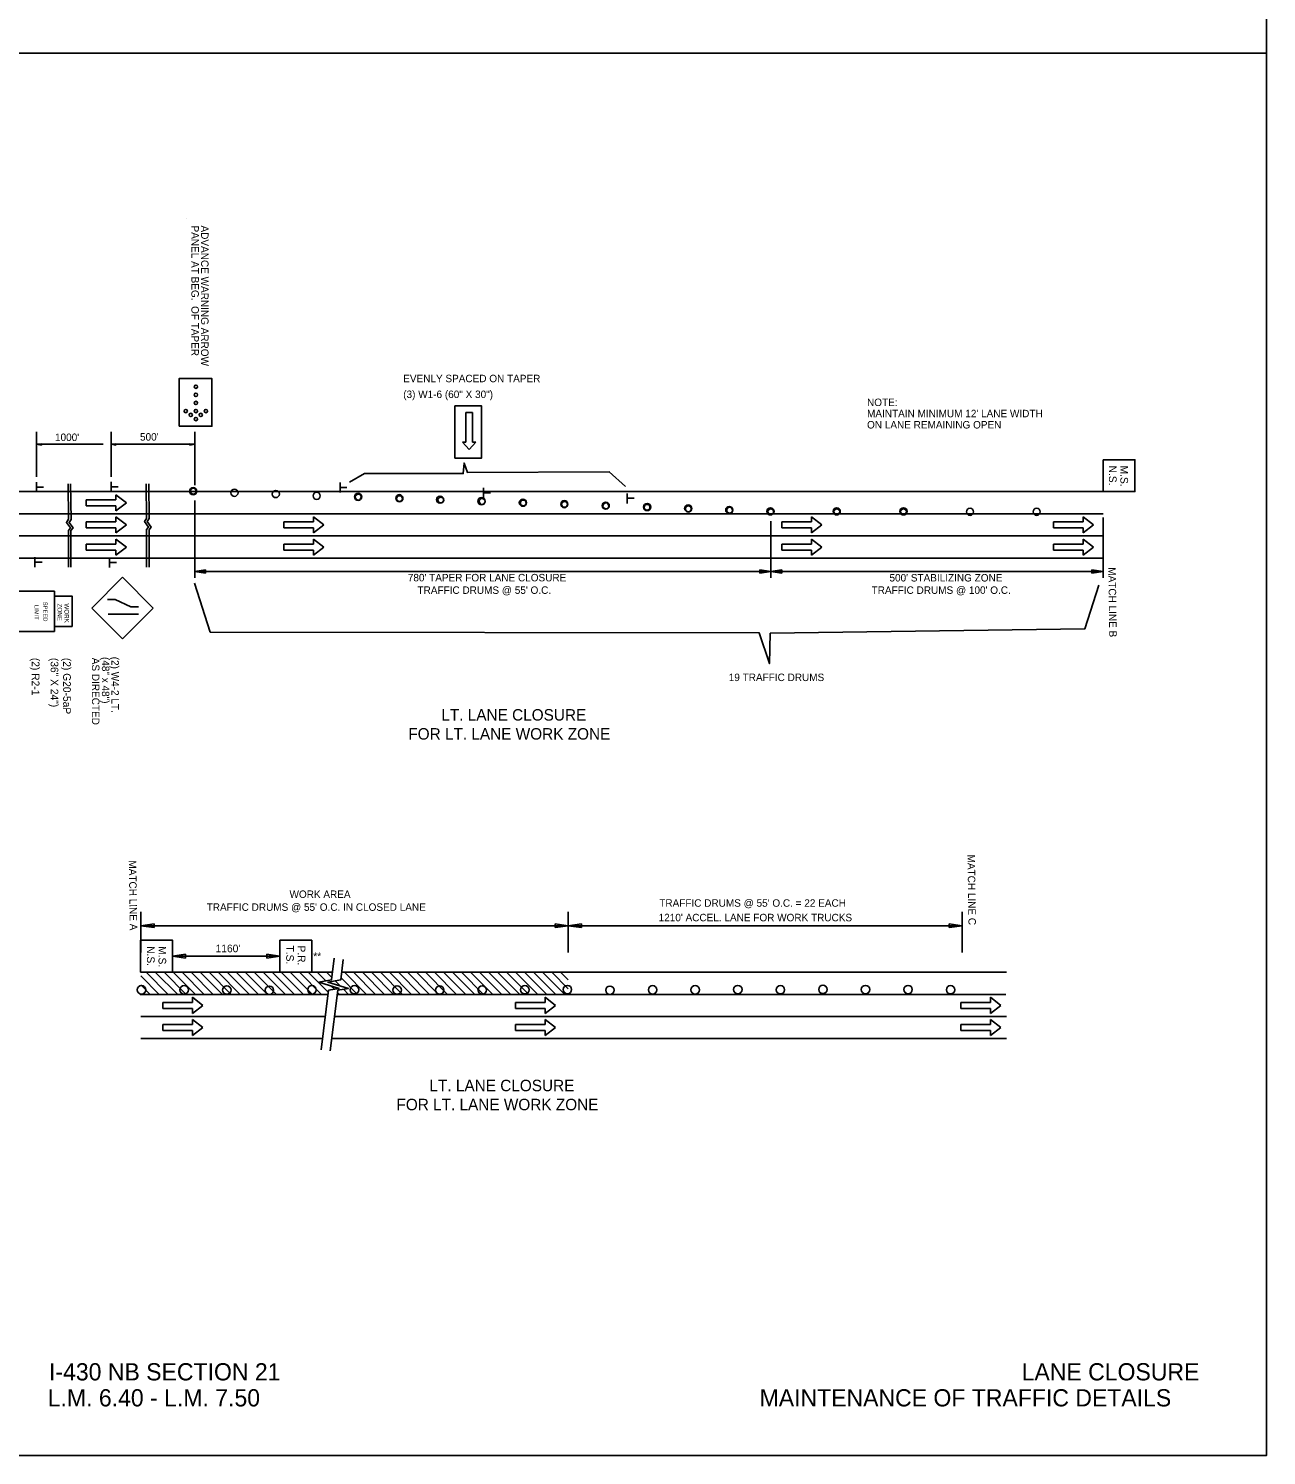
# Model space of a CAD drawing. Extents: x -100 to 745, y -1581 to -107.
# Drawn here: x 647.6 to 744.8, y -486.8 to -374.9 of the extents above; entities that cross this region are included whole.
import ezdxf

# ---------------------------------------------------------------- set-up
doc = ezdxf.new("R2010")
doc.units = 0
for name, color, linetype in [('Default', 7, 'Continuous'), ('R_Border', 7, 'Continuous'), ('R_Proposed Road', 7, 'Continuous'), ('R_ROW', 7, 'Continuous'), ('R_ROW Annot', 7, 'Continuous')]:
    doc.layers.add(name, color=color, linetype=linetype)

msp = doc.modelspace()

# ---------------------------------------------------------------- linework, layer by layer
at = {"layer": 'Default'}
for p, q in [((681.95, -404.99), (681.95, -407.32)), ((681.95, -404.99), (682.47, -404.99)), ((682.47, -404.99), (682.47, -407.32)), ((648.28, -406.5), (648.28, -410.02)), ((654.13, -406.5), (654.13, -410.02)), ((660.68, -406.5), (660.68, -410.69)), ((681.95, -407.32), (681.7, -407.32)), ((681.7, -407.32), (682.21, -407.89)), ((682.21, -407.89), (682.73, -407.32)), ((682.47, -407.32), (682.73, -407.32)), ((648.65, -407.43), (648.28, -407.48)), ((648.28, -407.48), (653.5, -407.48)), ((648.65, -407.54), (648.28, -407.48)), ((648.65, -407.44), (648.34, -407.48)), ((648.65, -407.53), (648.34, -407.48)), ((648.65, -407.45), (648.4, -407.48)), ((648.65, -407.52), (648.4, -407.48)), ((648.65, -407.45), (648.47, -407.48)), ((648.65, -407.51), (648.47, -407.48)), ((648.65, -407.46), (648.53, -407.48)), ((648.65, -407.5), (648.53, -407.48)), ((648.65, -407.47), (648.59, -407.48)), ((648.65, -407.49), (648.59, -407.48)), ((648.65, -407.54), (648.65, -407.43)), ((654.5, -407.43), (654.13, -407.48)), ((654.13, -407.48), (660.68, -407.48)), ((654.5, -407.54), (654.13, -407.48)), ((654.5, -407.44), (654.19, -407.48)), ((654.5, -407.53), (654.19, -407.48)), ((654.5, -407.45), (654.25, -407.48)), ((654.5, -407.52), (654.25, -407.48)), ((654.5, -407.45), (654.32, -407.48)), ((654.5, -407.51), (654.32, -407.48)), ((654.5, -407.46), (654.38, -407.48)), ((654.5, -407.5), (654.38, -407.48)), ((654.5, -407.47), (654.44, -407.48)), ((654.5, -407.49), (654.44, -407.48)), ((654.5, -407.54), (654.5, -407.43)), ((660.3, -407.43), (660.68, -407.48)), ((660.3, -407.43), (660.3, -407.54)), ((660.3, -407.44), (660.61, -407.48)), ((660.3, -407.45), (660.55, -407.48)), ((660.3, -407.45), (660.49, -407.48)), ((660.3, -407.46), (660.42, -407.48)), ((660.3, -407.47), (660.36, -407.48)), ((660.3, -407.54), (660.68, -407.48)), ((660.3, -407.5), (660.42, -407.48)), ((660.3, -407.52), (660.55, -407.48)), ((660.3, -407.53), (660.61, -407.48)), ((660.3, -407.51), (660.49, -407.48)), ((660.3, -407.49), (660.36, -407.48)), ((648.28, -411.22), (648.28, -410.44)), ((654.13, -411.2), (654.13, -410.42)), ((672.08, -410.47), (672.08, -411.25)), ((644.68, -411.19), (660.68, -411.19)), ((648.29, -410.83), (648.82, -410.83)), ((654.5, -411.83), (652.17, -411.83)), ((652.17, -411.83), (652.17, -412.3)), ((654.14, -410.81), (654.67, -410.81)), ((654.5, -411.43), (654.5, -411.83)), ((654.5, -411.43), (655.32, -412.06)), ((660.68, -411.19), (731.95, -411.19)), ((672.09, -410.86), (672.62, -410.86)), ((683.35, -410.9), (683.35, -411.68)), ((683.36, -411.29), (683.89, -411.29)), ((694.62, -411.33), (694.62, -412.11)), ((694.63, -411.71), (695.16, -411.71)), ((644.68, -412.93), (660.68, -412.93)), ((654.5, -412.3), (652.17, -412.3)), ((655.32, -412.06), (654.5, -412.7)), ((654.5, -412.3), (654.5, -412.7)), ((660.68, -417.94), (660.68, -411.9)), ((660.68, -412.93), (731.95, -412.93)), ((654.5, -413.57), (652.17, -413.57)), ((652.17, -413.57), (652.17, -414.04)), ((654.5, -414.04), (652.17, -414.04)), ((654.5, -413.17), (654.5, -413.57)), ((654.5, -413.17), (655.32, -413.8)), ((655.32, -413.8), (654.5, -414.43)), ((654.5, -414.04), (654.5, -414.43)), ((669.99, -413.57), (667.67, -413.57)), ((667.67, -413.57), (667.67, -414.04)), ((669.99, -414.04), (667.67, -414.04)), ((669.99, -413.17), (669.99, -413.57)), ((669.99, -413.17), (670.81, -413.8)), ((670.81, -413.8), (669.99, -414.43)), ((669.99, -414.04), (669.99, -414.43)), ((705.88, -417.94), (705.88, -413.51)), ((709.07, -413.57), (706.75, -413.57)), ((706.75, -413.57), (706.75, -414.04)), ((709.07, -414.04), (706.75, -414.04)), ((709.07, -413.17), (709.07, -413.57)), ((709.07, -413.17), (709.89, -413.8)), ((709.89, -413.8), (709.07, -414.43)), ((709.07, -414.04), (709.07, -414.43)), ((730.39, -413.57), (728.07, -413.57)), ((728.07, -413.57), (728.07, -414.04)), ((730.39, -414.04), (728.07, -414.04)), ((730.39, -413.17), (730.39, -413.57)), ((730.39, -413.17), (731.21, -413.8)), ((731.21, -413.8), (730.39, -414.43)), ((730.39, -414.04), (730.39, -414.43)), ((731.95, -413.23), (731.95, -417.95)), ((644.68, -414.67), (660.68, -414.67)), ((654.5, -414.91), (654.5, -415.3)), ((654.5, -414.91), (655.32, -415.54)), ((660.68, -414.67), (731.95, -414.67)), ((669.99, -414.91), (669.99, -415.3)), ((669.99, -414.91), (670.81, -415.54)), ((709.07, -414.91), (709.07, -415.3)), ((709.07, -414.91), (709.89, -415.54)), ((730.39, -414.91), (730.39, -415.3)), ((730.39, -414.91), (731.21, -415.54)), ((648.15, -417.11), (648.15, -416.32)), ((654.5, -415.3), (652.17, -415.3)), ((652.17, -415.3), (652.17, -415.78)), ((654.5, -415.78), (652.17, -415.78)), ((655.32, -415.54), (654.5, -416.17)), ((654.5, -415.78), (654.5, -416.17)), ((669.99, -415.3), (667.67, -415.3)), ((667.67, -415.3), (667.67, -415.78)), ((669.99, -415.78), (667.67, -415.78)), ((670.81, -415.54), (669.99, -416.17)), ((669.99, -415.78), (669.99, -416.17)), ((709.07, -415.3), (706.75, -415.3)), ((706.75, -415.3), (706.75, -415.78)), ((709.07, -415.78), (706.75, -415.78)), ((709.89, -415.54), (709.07, -416.17)), ((709.07, -415.78), (709.07, -416.17)), ((730.39, -415.3), (728.07, -415.3)), ((728.07, -415.3), (728.07, -415.78)), ((730.39, -415.78), (728.07, -415.78)), ((731.21, -415.54), (730.39, -416.17)), ((730.39, -415.78), (730.39, -416.17)), ((644.68, -416.41), (660.68, -416.41)), ((648.16, -416.72), (648.7, -416.72)), ((654, -417.13), (654, -416.35)), ((654.01, -416.74), (654.55, -416.74)), ((660.68, -416.41), (731.95, -416.41)), ((661.54, -417.32), (660.68, -417.45)), ((661.54, -417.58), (661.54, -417.32)), ((705.88, -417.45), (705.01, -417.32)), ((705.01, -417.32), (705.01, -417.58)), ((706.75, -417.32), (705.88, -417.45)), ((706.75, -417.58), (706.75, -417.32)), ((731.95, -417.45), (731.08, -417.32)), ((731.08, -417.32), (731.08, -417.58)), ((655.01, -417.91), (652.6, -420.32)), ((655.01, -417.91), (657.42, -420.32)), ((705.88, -417.45), (660.68, -417.45)), ((660.68, -417.45), (661.54, -417.58)), ((705.01, -417.58), (705.88, -417.45)), ((731.95, -417.45), (705.88, -417.45)), ((705.88, -417.45), (706.75, -417.58)), ((731.08, -417.58), (731.95, -417.45)), ((653.84, -419.66), (654.45, -419.66)), ((654.45, -419.66), (655.68, -420.22)), ((652.6, -420.32), (655.01, -422.73)), ((653.89, -420.79), (656.26, -420.79)), ((657.42, -420.32), (655.01, -422.73)), ((655.68, -420.22), (656.26, -420.22)), ((656.46, -444.16), (656.46, -447.35)), ((689.99, -444.16), (689.99, -447.35)), ((720.9, -444.16), (720.9, -447.35)), ((656.46, -445.24), (657.49, -445.09)), ((689.99, -445.24), (656.46, -445.24)), ((657.49, -445.39), (656.46, -445.24)), ((657.49, -445.09), (657.49, -445.39)), ((688.96, -445.39), (688.96, -445.09)), ((688.96, -445.09), (689.99, -445.24)), ((689.99, -445.24), (688.96, -445.39)), ((689.99, -445.24), (691.02, -445.09)), ((720.9, -445.24), (689.99, -445.24)), ((691.02, -445.39), (689.99, -445.24)), ((691.02, -445.09), (691.02, -445.39)), ((719.87, -445.39), (719.87, -445.09)), ((719.87, -445.09), (720.9, -445.24)), ((720.9, -445.24), (719.87, -445.39)), ((656.46, -445.9), (656.46, -447.35)), ((656.46, -446.83), (656.46, -447.35)), ((658.94, -447.63), (659.97, -447.47)), ((667.36, -447.63), (658.94, -447.63)), ((659.97, -447.78), (658.94, -447.63)), ((659.97, -447.47), (659.97, -447.78)), ((666.33, -447.78), (666.33, -447.47)), ((666.33, -447.47), (667.36, -447.63)), ((667.36, -447.63), (666.33, -447.78)), ((656.44, -448.88), (671.5, -448.88)), ((656.46, -449.18), (657.9, -450.62)), ((656.46, -449.88), (657.19, -450.62)), ((656.87, -448.88), (658.6, -450.62)), ((657.57, -448.88), (659.37, -450.67)), ((658.28, -448.88), (660.02, -450.62)), ((658.99, -448.88), (660.73, -450.62)), ((659.69, -448.88), (661.43, -450.62)), ((660.4, -448.88), (662.14, -450.62)), ((661.11, -448.88), (662.85, -450.62)), ((661.82, -448.88), (663.55, -450.62)), ((662.52, -448.88), (664.26, -450.62)), ((663.23, -448.88), (664.97, -450.62)), ((663.94, -448.88), (665.68, -450.62)), ((664.64, -448.88), (666.38, -450.62)), ((665.35, -448.88), (667.09, -450.62)), ((666.06, -448.88), (667.8, -450.62)), ((666.77, -448.88), (668.5, -450.62)), ((667.47, -448.88), (669.21, -450.62)), ((668.18, -448.88), (669.92, -450.62)), ((668.89, -448.88), (670.63, -450.62)), ((669.59, -448.88), (671.16, -450.45)), ((670.3, -448.88), (670.98, -449.56)), ((671.01, -448.88), (671.44, -449.31)), ((671.69, -449.56), (672.09, -449.96)), ((672.17, -449.33), (673.45, -450.62)), ((672.23, -448.88), (689.99, -448.88)), ((672.42, -448.88), (674.16, -450.62)), ((673.13, -448.88), (674.87, -450.62)), ((673.84, -448.88), (675.58, -450.62)), ((674.54, -448.88), (676.28, -450.62)), ((675.25, -448.88), (676.99, -450.62)), ((675.96, -448.88), (677.7, -450.62)), ((676.67, -448.88), (678.4, -450.62)), ((677.37, -448.88), (679.11, -450.62)), ((678.08, -448.88), (679.82, -450.62)), ((678.79, -448.88), (680.52, -450.62)), ((679.49, -448.88), (681.23, -450.62)), ((680.2, -448.88), (681.94, -450.62)), ((680.91, -448.88), (682.65, -450.62)), ((681.61, -448.88), (683.35, -450.62)), ((682.32, -448.88), (684.06, -450.62)), ((683.03, -448.88), (684.77, -450.62)), ((683.74, -448.88), (685.47, -450.62)), ((684.44, -448.88), (686.18, -450.62)), ((685.15, -448.88), (686.89, -450.62)), ((685.86, -448.88), (687.6, -450.62)), ((686.56, -448.88), (688.3, -450.62)), ((687.27, -448.88), (689.01, -450.62)), ((687.98, -448.88), (689.72, -450.62)), ((688.69, -448.88), (689.99, -450.19)), ((689.39, -448.88), (689.99, -449.48)), ((689.99, -448.88), (724.38, -448.88)), ((656.39, -450.62), (671.14, -450.62)), ((660.5, -451.25), (660.5, -450.85)), ((661.32, -451.49), (660.5, -450.85)), ((671.39, -449.97), (671.64, -450.22)), ((671.87, -450.62), (689.99, -450.62)), ((671.89, -450.47), (672.04, -450.62)), ((672.35, -450.22), (672.75, -450.62)), ((688.17, -451.25), (688.17, -450.85)), ((688.99, -451.49), (688.17, -450.85)), ((689.94, -450.62), (724.33, -450.62)), ((723.12, -451.25), (723.12, -450.85)), ((723.94, -451.49), (723.12, -450.85)), ((660.5, -451.25), (658.17, -451.25)), ((658.17, -451.72), (658.17, -451.25)), ((660.5, -451.72), (658.17, -451.72)), ((660.5, -452.12), (661.32, -451.49)), ((660.5, -452.12), (660.5, -451.72)), ((688.17, -451.25), (685.85, -451.25)), ((685.85, -451.72), (685.85, -451.25)), ((688.17, -451.72), (685.85, -451.72)), ((688.17, -452.12), (688.99, -451.49)), ((688.17, -452.12), (688.17, -451.72)), ((723.12, -451.25), (720.79, -451.25)), ((720.79, -451.72), (720.79, -451.25)), ((723.12, -451.72), (720.79, -451.72)), ((723.12, -452.12), (723.94, -451.49)), ((723.12, -452.12), (723.12, -451.72)), ((656.46, -452.35), (670.93, -452.35)), ((660.5, -452.99), (658.17, -452.99)), ((658.17, -453.46), (658.17, -452.99)), ((660.5, -452.99), (660.5, -452.59)), ((661.32, -453.22), (660.5, -452.59)), ((660.5, -453.86), (661.32, -453.22)), ((671.7, -452.35), (689.99, -452.35)), ((688.17, -452.99), (685.85, -452.99)), ((685.85, -453.46), (685.85, -452.99)), ((688.17, -452.99), (688.17, -452.59)), ((688.99, -453.22), (688.17, -452.59)), ((688.17, -453.86), (688.99, -453.22)), ((689.99, -452.35), (724.38, -452.35)), ((723.12, -452.99), (720.79, -452.99)), ((720.79, -453.46), (720.79, -452.99)), ((723.12, -452.99), (723.12, -452.59)), ((723.94, -453.22), (723.12, -452.59)), ((723.12, -453.86), (723.94, -453.22)), ((656.46, -454.09), (670.71, -454.09)), ((660.5, -453.46), (658.17, -453.46)), ((660.5, -453.86), (660.5, -453.46)), ((671.44, -454.09), (689.99, -454.09)), ((688.17, -453.46), (685.85, -453.46)), ((688.17, -453.86), (688.17, -453.46)), ((689.99, -454.09), (724.38, -454.09)), ((723.12, -453.46), (720.79, -453.46)), ((723.12, -453.86), (723.12, -453.46))]:
    msp.add_line(p, q, dxfattribs=at)
for points in [[(659.45, -406.06), (659.45, -402.33), (662.03, -402.33), (662.03, -406.06)], [(681.1, -408.56), (681.1, -404.47), (683.19, -404.47), (683.19, -408.56)], [(731.95, -408.69), (734.45, -408.69), (734.45, -411.19), (731.95, -411.19)], [(649.68, -422.17), (646.27, -422.17), (646.27, -419), (649.68, -419)], [(651.07, -421.78), (649.68, -421.78), (649.68, -419.4), (651.07, -419.4)], [(656.44, -446.38), (658.94, -446.38), (658.94, -448.88), (656.44, -448.88)], [(667.36, -446.38), (669.86, -446.38), (669.86, -448.88), (667.36, -448.88)]]:
    msp.add_lwpolyline(points, close=True, dxfattribs=at)
for points in [[(672.83, -410.45), (673.99, -409.77), (681.75, -409.77), (681.82, -408.95), (682.09, -409.7), (693.2, -409.63), (694.49, -410.79)], [(650.74, -410.58), (650.79, -413.36), (650.62, -413.6), (650.94, -414.03), (650.77, -414.23), (650.77, -417.12)], [(650.94, -410.58), (650.99, -413.37), (650.82, -413.61), (651.14, -414.04), (650.97, -414.24), (650.97, -417.12)], [(656.87, -410.58), (656.91, -413.29), (656.75, -413.54), (657.06, -413.97), (656.9, -414.17), (656.9, -417.12)], [(657.07, -410.58), (657.11, -413.3), (656.95, -413.54), (657.26, -413.98), (657.1, -414.18), (657.1, -417.12)], [(660.66, -418.38), (661.9, -422.21), (704.96, -422.26), (705.77, -424.68), (705.84, -422.3), (730.51, -421.96), (731.62, -418.53)], [(670.6, -454.96), (671.18, -450.3), (672.01, -450.16), (670.41, -449.67), (671.42, -449.48), (671.63, -447.79)], [(671.32, -455.05), (671.91, -450.3), (672.74, -450.16), (671.13, -449.67), (672.15, -449.48), (672.34, -447.89)]]:
    msp.add_lwpolyline(points, dxfattribs=at)
for centre, radius in [((660.77, -402.97), 0.131), ((660.77, -403.6), 0.131), ((659.98, -404.87), 0.131), ((660.37, -405.18), 0.131), ((660.77, -404.23), 0.131), ((660.77, -404.87), 0.131), ((661.16, -405.18), 0.131), ((661.56, -404.87), 0.131), ((660.77, -405.5), 0.131), ((660.56, -411.16), 0.281), ((660.57, -411.16), 0.229), ((663.8, -411.28), 0.281), ((667.04, -411.38), 0.281), ((670.25, -411.52), 0.281), ((673.5, -411.6), 0.281), ((673.51, -411.62), 0.229), ((676.74, -411.71), 0.281), ((676.75, -411.74), 0.229), ((679.93, -411.82), 0.281), ((679.99, -411.85), 0.229), ((683.18, -411.94), 0.281), ((683.23, -411.96), 0.229), ((686.43, -412.06), 0.281), ((686.46, -412.08), 0.229), ((689.68, -412.17), 0.281), ((689.7, -412.19), 0.229), ((692.93, -412.29), 0.281), ((692.94, -412.31), 0.229), ((696.18, -412.4), 0.281), ((696.17, -412.42), 0.229), ((699.4, -412.51), 0.281), ((699.41, -412.54), 0.229), ((702.62, -412.63), 0.281), ((702.65, -412.65), 0.229), ((705.85, -412.74), 0.281), ((705.87, -412.77), 0.229), ((705.88, -412.77), 0.229), ((711.05, -412.74), 0.281), ((711.06, -412.77), 0.229), ((716.29, -412.74), 0.281), ((716.29, -412.77), 0.229), ((721.51, -412.77), 0.281), ((726.74, -412.77), 0.281), ((709.97, -450.23), 0.333), ((656.51, -450.27), 0.333), ((659.85, -450.27), 0.333), ((663.2, -450.28), 0.333), ((666.54, -450.3), 0.333), ((669.88, -450.27), 0.333), ((673.22, -450.26), 0.333), ((676.56, -450.28), 0.333), ((679.9, -450.28), 0.333), ((683.24, -450.28), 0.333), ((686.58, -450.26), 0.333), ((689.92, -450.25), 0.333), ((693.26, -450.3), 0.333), ((696.61, -450.27), 0.333), ((699.95, -450.27), 0.333), ((703.29, -450.25), 0.333), ((706.63, -450.26), 0.333), ((713.31, -450.25), 0.333), ((716.65, -450.25), 0.333), ((719.99, -450.26), 0.333)]:
    msp.add_circle(centre, radius, dxfattribs=at)
at = {"layer": 'R_Proposed Road'}
for points in [[(574.77, -266.79), (574.77, -376.79), (744.77, -376.79), (744.77, -266.79)], [(574.77, -376.79), (574.77, -486.79), (744.77, -486.79), (744.77, -376.79)]]:
    msp.add_lwpolyline(points, close=True, dxfattribs=at)
at = {"layer": 'R_ROW Annot'}
msp.add_line((660.05, -389.8), (660.05, -389.8), dxfattribs=at)
msp.add_line((660.05, -389.8), (660.05, -389.8), dxfattribs=at)

# ---------------------------------------------------------------- texts
at = {"layer": 'Default'}
for s, height, rotation, p in [('PANEL AT BEG.  OF TAPER', 0.5862, 270, (660.42, -390.32)), ('ADVANCE WARNING ARROW', 0.5862, 270, (661.18, -390.32)), ('EVENLY SPACED ON TAPER', 0.5862, 359.9925, (677.04, -402.61)), ('(3) W1-6 (60" X 30")', 0.5862, 359.9925, (677.04, -403.85)), ('N.S.', 0.6, 270, (732.41, -409.15)), ('M.S.', 0.6, 270, (733.31, -409.15)), ('MATCH LINE B', 0.5862, 270.8059, (732.36, -417.13)), ('LIMIT', 0.33, 270, (648.12, -420.08)), ('SPEED', 0.33, 270, (648.8, -419.83)), ('ZONE', 0.354, 270.1004, (649.92, -419.97)), ('WORK', 0.354, 270.1004, (650.46, -419.96)), ('(2) R2-1', 0.6, 270, (647.9, -424.23)), ('(36" X 24")', 0.6, 270, (649.38, -424.23)), ('(2) G20-5aP', 0.6, 270, (650.36, -424.23)), ('AS DIRECTED ', 0.5862, 270, (652.62, -424.22)), ('(48" x 48")', 0.5862, 270, (653.4, -424.16)), ('(2) W4-2 LT.', 0.5862, 270, (654.15, -424.14)), ('MATCH LINE C', 0.5862, 270.8059, (721.31, -439.66)), ('MATCH LINE A', 0.5862, 270.8059, (655.51, -440.12)), ('N.S.', 0.6, 270, (656.94, -446.84)), ('M.S.', 0.6, 270, (657.84, -446.84)), ('T.S.', 0.6, 270, (667.86, -446.79)), ('P.R.', 0.6, 270, (668.76, -446.79))]:
    msp.add_text(s, height=height, rotation=rotation, dxfattribs=at).set_placement(p)
for s, height, p in [('NOTE:', 0.586, (713.43, -404.48)), ("MAINTAIN MINIMUM 12' LANE WIDTH", 0.5862, (713.43, -405.36)), ('ON LANE REMAINING OPEN', 0.5862, (713.43, -406.24)), ("1000'", 0.586, (649.72, -407.22)), ("500'", 0.586, (656.39, -407.19)), ("780' TAPER FOR LANE CLOSURE", 0.5862, (677.4, -418.23)), ("500' STABILIZING ZONE", 0.5862, (715.19, -418.24)), ("TRAFFIC DRUMS @ 55' O.C.", 0.5862, (678.16, -419.21)), ("TRAFFIC DRUMS @ 100' O.C.", 0.5862, (713.79, -419.21)), ('19 TRAFFIC DRUMS', 0.5862, (702.58, -426.05)), ('WORK AREA', 0.586, (668.12, -443.06)), ("TRAFFIC DRUMS @ 55' O.C. = 22 EACH", 0.5862, (697.13, -443.75)), ("TRAFFIC DRUMS @ 55' O.C. IN CLOSED LANE", 0.5862, (661.62, -444.07)), ("1210' ACCEL. LANE FOR WORK TRUCKS", 0.5862, (697.08, -444.89)), ("1160'", 0.6, (662.32, -447.32)), ('**', 0.6, (669.98, -447.93))]:
    msp.add_text(s, height=height, dxfattribs=at).set_placement(p)
at = {"layer": 'R_Border'}
for s, p in [('I-430 NB SECTION 21', (649.25, -480.9)), ('LANE CLOSURE', (725.56, -480.9)), ('L.M. 6.40 - L.M. 7.50', (649.15, -482.94)), ('MAINTENANCE OF TRAFFIC DETAILS', (705, -482.94))]:
    msp.add_text(s, height=1.35, dxfattribs=at).set_placement(p)
at = {"layer": 'R_ROW'}
for s, p in [('LT. LANE CLOSURE ', (680.03, -429.15)), ('FOR LT. LANE WORK ZONE', (677.44, -430.64)), ('LT. LANE CLOSURE ', (679.1, -458.22)), ('FOR LT. LANE WORK ZONE', (676.51, -459.71))]:
    msp.add_text(s, height=0.9, dxfattribs=at).set_placement(p)

doc.saveas('drawing.dxf')
